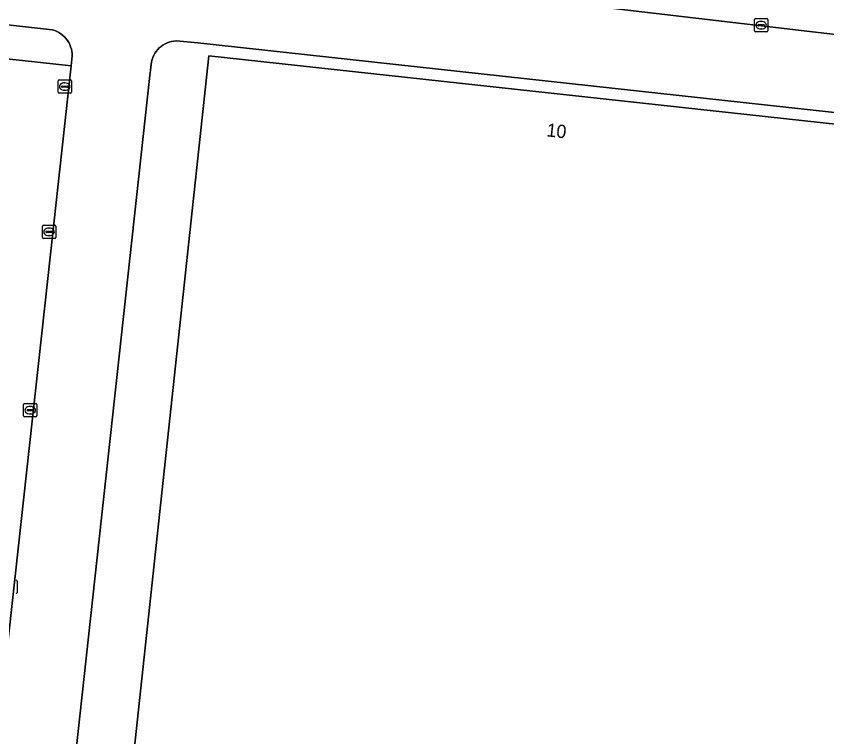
# Model space of a CAD drawing. Extents: x 162184 to 163154, y 385507 to 386516.
# Drawn here: x 162544.8 to 162606.1, y 386358.9 to 386413.4 of the extents above; entities that cross this region are included whole.
import ezdxf

# ---------------------------------------------------------------- set-up
doc = ezdxf.new("R2010")
doc.units = 0
for name, color, linetype in [('IMGEO_Groenvoorziening', 7, 'Continuous'), ('IMGEO_Haag', 7, 'Continuous'), ('IMGEO_Kolk', 7, 'Continuous'), ('IMGEO_Pand', 7, 'Continuous'), ('IMGEO_Pand_nummerreeks', 7, 'Continuous'), ('IMGEO_Parkeervlak_open', 7, 'Continuous'), ('IMGEO_Rijbaan_lokaal_open', 7, 'Continuous'), ('IMGEO_Voetpad_open', 7, 'Continuous')]:
    doc.layers.add(name, color=color, linetype=linetype)

msp = doc.modelspace()

# ---------------------------------------------------------------- linework, layer by layer
at = {"layer": 'IMGEO_Groenvoorziening'}
msp.add_lwpolyline([(162538.075, 386410.846), (162548.989, 386409.64), (162549.073, 386410.4), (162549.064, 386410.577), (162549.04, 386410.751), (162549.001, 386410.924), (162548.947, 386411.092), (162548.88, 386411.255), (162548.799, 386411.412), (162548.704, 386411.561), (162548.598, 386411.702), (162548.479, 386411.833), (162548.35, 386411.954), (162548.212, 386412.063), (162548.064, 386412.16), (162547.909, 386412.244), (162547.747, 386412.315), (162547.58, 386412.372), (162540.07, 386413.207)], dxfattribs=at)
at = {"layer": 'IMGEO_Haag'}
msp.add_lwpolyline([(162538.075, 386410.846), (162548.989, 386409.64), (162549.073, 386410.4), (162549.064, 386410.577), (162549.04, 386410.751), (162549.001, 386410.924), (162548.947, 386411.092), (162548.88, 386411.255), (162548.799, 386411.412), (162548.704, 386411.561), (162548.598, 386411.702), (162548.479, 386411.833), (162548.35, 386411.954), (162548.212, 386412.063), (162548.064, 386412.16), (162547.909, 386412.244), (162547.747, 386412.315), (162547.58, 386412.372), (162540.07, 386413.207)], dxfattribs=at)
at = {"layer": 'IMGEO_Kolk'}
for p, q in [((162600.753, 386413.225), (162601.605, 386413.225)), ((162600.678, 386412.299), (162600.678, 386413.151)), ((162600.937, 386412.719), (162600.937, 386412.731)), ((162601.375, 386412.682), (162600.977, 386412.682)), ((162600.98, 386412.768), (162601.378, 386412.768)), ((162601.166, 386413.005), (162601.191, 386413.005)), ((162601.421, 386412.731), (162601.421, 386412.719)), ((162601.679, 386413.151), (162601.679, 386412.299)), ((162601.605, 386412.225), (162600.753, 386412.225)), ((162601.189, 386412.445), (162601.164, 386412.445)), ((162548, 386407.658), (162548, 386408.51)), ((162548.075, 386408.584), (162548.927, 386408.584)), ((162548.488, 386408.364), (162548.513, 386408.364)), ((162549.001, 386408.51), (162549.001, 386407.658)), ((162548.259, 386408.078), (162548.259, 386408.09)), ((162548.697, 386408.041), (162548.299, 386408.041)), ((162548.302, 386408.127), (162548.7, 386408.127)), ((162548.511, 386407.804), (162548.486, 386407.804)), ((162548.743, 386408.09), (162548.743, 386408.078)), ((162548.927, 386407.584), (162548.075, 386407.584)), ((162546.812, 386396.675), (162546.812, 386397.527)), ((162546.887, 386397.601), (162547.739, 386397.601)), ((162547.3, 386397.381), (162547.325, 386397.381)), ((162547.813, 386397.527), (162547.813, 386396.675)), ((162547.071, 386397.095), (162547.071, 386397.107)), ((162547.509, 386397.058), (162547.111, 386397.058)), ((162547.114, 386397.144), (162547.512, 386397.144)), ((162547.323, 386396.821), (162547.298, 386396.821)), ((162547.555, 386397.107), (162547.555, 386397.095)), ((162547.739, 386396.601), (162546.887, 386396.601)), ((162545.387, 386383.19), (162545.387, 386384.042)), ((162545.462, 386384.116), (162546.314, 386384.116)), ((162545.875, 386383.896), (162545.9, 386383.896)), ((162546.388, 386384.042), (162546.388, 386383.19)), ((162545.646, 386383.61), (162545.646, 386383.622)), ((162546.084, 386383.573), (162545.686, 386383.573)), ((162545.689, 386383.659), (162546.087, 386383.659)), ((162545.898, 386383.336), (162545.873, 386383.336)), ((162546.13, 386383.622), (162546.13, 386383.61)), ((162546.314, 386383.116), (162545.462, 386383.116)), ((162544.902, 386370.697), (162544.902, 386369.845))]:
    msp.add_line(p, q, dxfattribs=at)
for points in [[(162600.753, 386413.225), (162601.605, 386413.225)], [(162600.678, 386412.299), (162600.678, 386413.151)], [(162601.679, 386413.151), (162601.679, 386412.299)], [(162601.605, 386412.225), (162600.753, 386412.225)], [(162548, 386407.658), (162548, 386408.51)], [(162548.075, 386408.584), (162548.927, 386408.584)], [(162549.001, 386408.51), (162549.001, 386407.658)], [(162548.927, 386407.584), (162548.075, 386407.584)], [(162546.812, 386396.675), (162546.812, 386397.527)], [(162546.887, 386397.601), (162547.739, 386397.601)], [(162547.813, 386397.527), (162547.813, 386396.675)], [(162547.739, 386396.601), (162546.887, 386396.601)], [(162545.387, 386383.19), (162545.387, 386384.042)], [(162545.462, 386384.116), (162546.314, 386384.116)], [(162546.388, 386384.042), (162546.388, 386383.19)], [(162546.314, 386383.116), (162545.462, 386383.116)], [(162544.902, 386370.697), (162544.902, 386369.845)]]:
    msp.add_lwpolyline(points, dxfattribs=at)
for centre, radius, start, end in [((162600.755, 386413.149), 0.0765, 91.55205, 178.44795), ((162600.755, 386413.149), 0.0765, 91.55205, 178.44795), ((162601.603, 386413.149), 0.0765, 1.55205, 88.44795), ((162601.603, 386413.149), 0.0765, 1.55205, 88.44795), ((162600.977, 386412.728), 0.0403, 85.87752, 175.75265), ((162600.974, 386412.718), 0.0366, 178.93798, 274.71019), ((162601.378, 386412.725), 0.043, 264.86636, 352.45326), ((162601.382, 386412.73), 0.0386, 1.73085, 96.63898), ((162600.755, 386412.301), 0.0765, 181.55205, 268.44795), ((162600.755, 386412.301), 0.0765, 181.55205, 268.44795), ((162601.603, 386412.301), 0.0765, 271.55205, 358.44795), ((162601.603, 386412.301), 0.0765, 271.55205, 358.44795), ((162548.077, 386408.508), 0.0765, 91.55205, 178.44795), ((162548.077, 386408.508), 0.0765, 91.55205, 178.44795), ((162548.925, 386408.508), 0.0765, 1.55205, 88.44795), ((162548.925, 386408.508), 0.0765, 1.55205, 88.44795), ((162548.299, 386408.087), 0.0403, 85.87752, 175.75265), ((162548.296, 386408.077), 0.0366, 178.93798, 274.71019), ((162548.7, 386408.084), 0.043, 264.86636, 352.45326), ((162548.704, 386408.089), 0.0386, 1.73085, 96.63898), ((162548.077, 386407.66), 0.0765, 181.55205, 268.44795), ((162548.077, 386407.66), 0.0765, 181.55205, 268.44795), ((162548.925, 386407.66), 0.0765, 271.55205, 358.44795), ((162548.925, 386407.66), 0.0765, 271.55205, 358.44795), ((162546.889, 386397.525), 0.0765, 91.55205, 178.44795), ((162546.889, 386397.525), 0.0765, 91.55205, 178.44795), ((162547.737, 386397.525), 0.0765, 1.55205, 88.44795), ((162547.737, 386397.525), 0.0765, 1.55205, 88.44795), ((162546.889, 386396.677), 0.0765, 181.55205, 268.44795), ((162546.889, 386396.677), 0.0765, 181.55205, 268.44795), ((162547.111, 386397.104), 0.0403, 85.87752, 175.75265), ((162547.108, 386397.094), 0.0366, 178.93798, 274.71019), ((162547.512, 386397.101), 0.043, 264.86636, 352.45326), ((162547.516, 386397.106), 0.0386, 1.73085, 96.63898), ((162547.737, 386396.677), 0.0765, 271.55205, 358.44795), ((162547.737, 386396.677), 0.0765, 271.55205, 358.44795), ((162545.464, 386384.04), 0.0765, 91.55205, 178.44795), ((162545.464, 386384.04), 0.0765, 91.55205, 178.44795), ((162546.312, 386384.04), 0.0765, 1.55205, 88.44795), ((162546.312, 386384.04), 0.0765, 1.55205, 88.44795), ((162545.464, 386383.192), 0.0765, 181.55205, 268.44795), ((162545.464, 386383.192), 0.0765, 181.55205, 268.44795), ((162545.686, 386383.619), 0.0403, 85.87752, 175.75265), ((162545.683, 386383.609), 0.0366, 178.93798, 274.71019), ((162546.087, 386383.616), 0.043, 264.86636, 352.45326), ((162546.091, 386383.621), 0.0386, 1.73085, 96.63898), ((162546.312, 386383.192), 0.0765, 271.55205, 358.44795), ((162546.312, 386383.192), 0.0765, 271.55205, 358.44795), ((162544.826, 386370.695), 0.0765, 1.55205, 88.44795), ((162544.826, 386370.695), 0.0765, 1.55205, 88.44795), ((162544.826, 386369.847), 0.0765, 271.55205, 358.44795), ((162544.826, 386369.847), 0.0765, 271.55205, 358.44795)]:
    msp.add_arc(centre, radius, start, end, dxfattribs=at)
for centre, major_axis, ratio, start_param, end_param in [((162601.165, 386412.725), (-0.387, 0.002), 0.722429, 4.712389, 7.853982), ((162601.19, 386412.725), (-0.39, 0.002), 0.717154, 1.570796, 4.712389), ((162548.487, 386408.084), (-0.387, 0.002), 0.722429, 4.712389, 7.853982), ((162548.512, 386408.084), (-0.39, 0.002), 0.717154, 1.570796, 4.712389), ((162547.299, 386397.101), (-0.387, 0.002), 0.722429, 4.712389, 7.853982), ((162547.324, 386397.101), (-0.39, 0.002), 0.717154, 1.570796, 4.712389), ((162545.874, 386383.616), (-0.387, 0.002), 0.722429, 4.712389, 7.853982), ((162545.899, 386383.616), (-0.39, 0.002), 0.717154, 1.570796, 4.712389)]:
    msp.add_ellipse(centre, major_axis=major_axis, ratio=ratio, start_param=start_param, end_param=end_param, dxfattribs=at)
at = {"layer": 'IMGEO_Pand'}
msp.add_lwpolyline([(162554.466, 386351.14), (162551.394, 386351.387), (162550.959, 386347.389), (162552.51, 386347.22), (162550.572, 386329.166), (162570.2, 386327.044), (162570.371, 386328.537), (162584.259, 386326.946), (162584.111, 386325.529), (162603.751, 386323.413), (162606.924, 386352.615), (162605.495, 386352.753), (162605.841, 386355.904), (162607.28, 386355.744), (162608.842, 386355.576), (162609.275, 386359.57), (162607.724, 386359.738), (162612.582, 386404.614), (162559.406, 386410.398), (162553.579, 386356.265), (162555.001, 386356.112), (162554.962, 386355.747), (162554.494, 386351.401)], close=True, dxfattribs=at)
at = {"layer": 'IMGEO_Parkeervlak_open'}
for points in [[(162563.323, 386417.145), (162619.479, 386410.523), (162619.784, 386413.265), (162563.553, 386419.326)], [(162548.989, 386409.64), (162538.075, 386410.846), (162532.715, 386362.026), (162532.943, 386362.003), (162543.625, 386360.744)]]:
    msp.add_lwpolyline(points, close=True, dxfattribs=at)
at = {"layer": 'IMGEO_Rijbaan_lokaal_open'}
for points in [[(162619.479, 386410.523), (162563.323, 386417.145)], [(162540.07, 386413.207), (162547.58, 386412.372), (162547.747, 386412.315), (162547.909, 386412.244), (162548.064, 386412.16), (162548.212, 386412.063), (162548.35, 386411.954), (162548.479, 386411.833), (162548.598, 386411.702), (162548.704, 386411.561), (162548.799, 386411.412), (162548.88, 386411.255), (162548.947, 386411.092), (162549.001, 386410.924), (162549.04, 386410.751), (162549.064, 386410.577), (162549.073, 386410.4), (162548.989, 386409.64), (162543.625, 386360.744)], [(162554.911, 386408.696), (162555.064, 386409.948), (162555.106, 386410.12), (162555.162, 386410.287), (162555.234, 386410.448), (162555.319, 386410.602), (162555.418, 386410.748), (162555.53, 386410.884), (162555.654, 386411.01), (162555.788, 386411.124), (162555.932, 386411.225), (162556.085, 386411.314), (162556.245, 386411.388), (162556.411, 386411.447), (162556.581, 386411.491), (162556.755, 386411.52), (162556.931, 386411.533), (162558.579, 386411.402), (162614.804, 386405.248)], [(162605.702, 386321.861), (162549.69, 386327.963), (162551.757, 386346.596), (162548.152, 386346.88), (162554.911, 386408.696)]]:
    msp.add_lwpolyline(points, dxfattribs=at)
at = {"layer": 'IMGEO_Voetpad_open'}
msp.add_lwpolyline([(162614.804, 386405.248), (162558.579, 386411.402), (162556.931, 386411.533), (162556.755, 386411.52), (162556.581, 386411.491), (162556.411, 386411.447), (162556.245, 386411.388), (162556.085, 386411.314), (162555.932, 386411.225), (162555.788, 386411.124), (162555.654, 386411.01), (162555.53, 386410.884), (162555.418, 386410.748), (162555.319, 386410.602), (162555.234, 386410.448), (162555.162, 386410.287), (162555.106, 386410.12), (162555.064, 386409.948), (162554.911, 386408.696), (162548.152, 386346.88), (162551.757, 386346.596)], dxfattribs=at)
msp.add_lwpolyline([(162603.751, 386323.413), (162584.111, 386325.529), (162584.259, 386326.946), (162570.371, 386328.537), (162570.2, 386327.044), (162550.572, 386329.166), (162552.51, 386347.22), (162550.959, 386347.389), (162551.394, 386351.387), (162554.466, 386351.14), (162554.494, 386351.401), (162554.962, 386355.747), (162555.001, 386356.112), (162553.579, 386356.265), (162559.406, 386410.398), (162612.582, 386404.614), (162607.724, 386359.738), (162609.275, 386359.57), (162608.842, 386355.576), (162607.28, 386355.744), (162605.841, 386355.904), (162605.495, 386352.753), (162606.924, 386352.615)], close=True, dxfattribs=at)

# ---------------------------------------------------------------- texts
at = {"layer": 'IMGEO_Pand_nummerreeks'}
msp.add_text('10', height=1, rotation=353.79229, dxfattribs=at).set_placement((162584.911, 386404.325))

doc.saveas('drawing.dxf')
